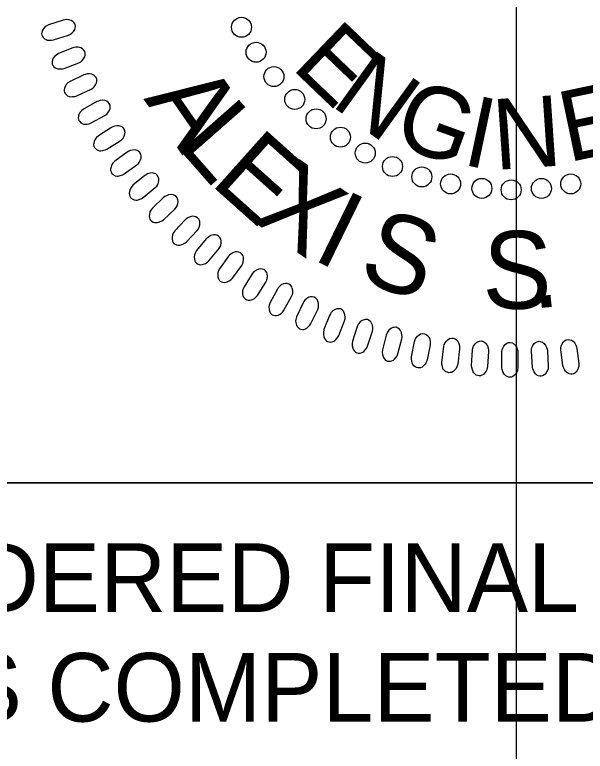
# Model space of a CAD drawing. Extents: x 497599 to 513368, y 404140 to 476034.
# Drawn here: x 507268.5 to 507314.2, y 439677.1 to 439736.2 of the extents above; entities that cross this region are included whole.
import ezdxf

# ---------------------------------------------------------------- set-up
doc = ezdxf.new("R2010")
doc.units = 0
for name, color, linetype in [('Sheet Layout Profile Border Port 2', 7, 'Continuous'), ('Sheet PE Seal Cell', 7, 'Continuous'), ('Sheet Profile CELL', 7, 'Continuous'), ('Sheet Sticker Exception Certification CELL', 7, 'Continuous')]:
    doc.layers.add(name, color=color, linetype=linetype)

msp = doc.modelspace()

# ---------------------------------------------------------------- linework, layer by layer
at = {"layer": 'Sheet Layout Profile Border Port 2'}
msp.add_lwpolyline([(505908.678, 439836.144), (507308.678, 439836.144), (507308.678, 439336.144), (505908.678, 439336.144)], close=True, dxfattribs=at)
at = {"layer": 'Sheet PE Seal Cell'}
for points in [[(507272.361, 439735.737), (507271.194, 439735.358), (507270.997, 439735.255), (507270.88, 439735.163), (507270.753, 439735.003), (507270.679, 439734.877), (507270.638, 439734.746), (507270.632, 439734.634), (507270.648, 439734.521), (507270.702, 439734.421), (507270.767, 439734.316), (507270.856, 439734.235), (507270.983, 439734.167), (507271.077, 439734.134), (507271.241, 439734.116), (507271.43, 439734.115), (507271.589, 439734.143), (507272.786, 439734.523), (507272.94, 439734.597), (507273.059, 439734.683), (507273.183, 439734.818), (507273.281, 439734.967), (507273.328, 439735.084), (507273.336, 439735.252), (507273.309, 439735.401), (507273.225, 439735.53), (507273.145, 439735.615), (507273.011, 439735.705), (507272.813, 439735.766), (507272.621, 439735.775), (507272.489, 439735.763)], [(507273.12, 439733.5), (507271.979, 439733.049), (507271.788, 439732.933), (507271.677, 439732.833), (507271.561, 439732.667), (507271.495, 439732.536), (507271.462, 439732.402), (507271.464, 439732.291), (507271.486, 439732.179), (507271.546, 439732.082), (507271.618, 439731.982), (507271.711, 439731.906), (507271.843, 439731.846), (507271.939, 439731.82), (507272.103, 439731.812), (507272.292, 439731.823), (507272.449, 439731.86), (507273.62, 439732.315), (507273.77, 439732.399), (507273.883, 439732.492), (507273.998, 439732.634), (507274.087, 439732.789), (507274.125, 439732.909), (507274.123, 439733.077), (507274.086, 439733.224), (507273.995, 439733.347), (507273.909, 439733.427), (507273.77, 439733.509), (507273.569, 439733.556), (507273.377, 439733.554), (507273.245, 439733.533)], [(507274.019, 439731.341), (507272.909, 439730.819), (507272.726, 439730.691), (507272.622, 439730.585), (507272.517, 439730.411), (507272.458, 439730.276), (507272.434, 439730.141), (507272.443, 439730.029), (507272.472, 439729.919), (507272.538, 439729.827), (507272.616, 439729.731), (507272.715, 439729.662), (507272.85, 439729.61), (507272.947, 439729.589), (507273.111, 439729.592), (507273.299, 439729.615), (507273.453, 439729.662), (507274.593, 439730.189), (507274.737, 439730.282), (507274.844, 439730.382), (507274.95, 439730.531), (507275.03, 439730.692), (507275.06, 439730.814), (507275.048, 439730.982), (507275.002, 439731.126), (507274.902, 439731.243), (507274.812, 439731.317), (507274.668, 439731.39), (507274.464, 439731.425), (507274.273, 439731.41), (507274.143, 439731.382)], [(507275.067, 439729.192), (507273.991, 439728.601), (507273.817, 439728.463), (507273.72, 439728.35), (507273.625, 439728.17), (507273.576, 439728.031), (507273.56, 439727.895), (507273.575, 439727.784), (507273.612, 439727.676), (507273.683, 439727.588), (507273.768, 439727.498), (507273.87, 439727.434), (507274.008, 439727.391), (507274.107, 439727.377), (507274.27, 439727.39), (507274.456, 439727.424), (507274.607, 439727.481), (507275.712, 439728.079), (507275.85, 439728.181), (507275.95, 439728.288), (507276.047, 439728.443), (507276.115, 439728.608), (507276.139, 439728.732), (507276.115, 439728.898), (507276.06, 439729.039), (507275.954, 439729.151), (507275.86, 439729.218), (507275.711, 439729.282), (507275.505, 439729.305), (507275.315, 439729.277), (507275.187, 439729.241)], [(507276.223, 439727.117), (507275.187, 439726.46), (507275.021, 439726.311), (507274.932, 439726.192), (507274.848, 439726.006), (507274.808, 439725.866), (507274.8, 439725.728), (507274.823, 439725.619), (507274.866, 439725.513), (507274.943, 439725.43), (507275.032, 439725.345), (507275.139, 439725.288), (507275.279, 439725.253), (507275.378, 439725.245), (507275.541, 439725.269), (507275.724, 439725.315), (507275.871, 439725.381), (507276.937, 439726.047), (507277.068, 439726.157), (507277.162, 439726.271), (507277.248, 439726.431), (507277.306, 439726.6), (507277.322, 439726.725), (507277.288, 439726.89), (507277.225, 439727.027), (507277.111, 439727.132), (507277.013, 439727.193), (507276.86, 439727.247), (507276.653, 439727.257), (507276.465, 439727.218), (507276.34, 439727.174)], [(507277.5, 439725.142), (507276.506, 439724.421), (507276.351, 439724.262), (507276.268, 439724.138), (507276.197, 439723.947), (507276.166, 439723.804), (507276.167, 439723.667), (507276.196, 439723.559), (507276.246, 439723.456), (507276.328, 439723.377), (507276.422, 439723.298), (507276.532, 439723.248), (507276.675, 439723.223), (507276.774, 439723.221), (507276.935, 439723.254), (507277.115, 439723.311), (507277.258, 439723.387), (507278.278, 439724.119), (507278.403, 439724.237), (507278.489, 439724.356), (507278.566, 439724.522), (507278.613, 439724.694), (507278.621, 439724.82), (507278.577, 439724.982), (507278.505, 439725.115), (507278.385, 439725.212), (507278.283, 439725.268), (507278.127, 439725.312), (507277.92, 439725.309), (507277.735, 439725.258), (507277.613, 439725.206)], [(507278.903, 439723.261), (507277.957, 439722.479), (507277.812, 439722.311), (507277.738, 439722.181), (507277.678, 439721.987), (507277.656, 439721.842), (507277.666, 439721.705), (507277.702, 439721.599), (507277.758, 439721.5), (507277.845, 439721.426), (507277.944, 439721.353), (507278.056, 439721.31), (507278.2, 439721.294), (507278.3, 439721.298), (507278.458, 439721.342), (507278.634, 439721.41), (507278.772, 439721.494), (507279.745, 439722.289), (507279.861, 439722.414), (507279.94, 439722.538), (507280.006, 439722.709), (507280.043, 439722.884), (507280.042, 439723.01), (507279.988, 439723.169), (507279.908, 439723.297), (507279.782, 439723.386), (507279.677, 439723.435), (507279.519, 439723.47), (507279.313, 439723.454), (507279.131, 439723.392), (507279.012, 439723.332)], [(507280.413, 439721.49), (507279.518, 439720.651), (507279.384, 439720.474), (507279.318, 439720.34), (507279.271, 439720.142), (507279.258, 439719.996), (507279.276, 439719.86), (507279.319, 439719.756), (507279.381, 439719.661), (507279.472, 439719.593), (507279.576, 439719.526), (507279.691, 439719.49), (507279.835, 439719.483), (507279.934, 439719.493), (507280.09, 439719.547), (507280.262, 439719.626), (507280.393, 439719.718), (507281.314, 439720.573), (507281.423, 439720.706), (507281.494, 439720.834), (507281.549, 439721.008), (507281.574, 439721.185), (507281.565, 439721.311), (507281.502, 439721.467), (507281.414, 439721.589), (507281.283, 439721.671), (507281.174, 439721.713), (507281.015, 439721.738), (507280.81, 439721.709), (507280.632, 439721.635), (507280.518, 439721.568)], [(507282.149, 439719.712), (507281.308, 439718.818), (507281.185, 439718.633), (507281.128, 439718.495), (507281.093, 439718.295), (507281.089, 439718.147), (507281.116, 439718.013), (507281.165, 439717.913), (507281.233, 439717.821), (507281.328, 439717.759), (507281.436, 439717.699), (507281.553, 439717.67), (507281.698, 439717.672), (507281.796, 439717.689), (507281.948, 439717.752), (507282.114, 439717.842), (507282.24, 439717.942), (507283.106, 439718.854), (507283.205, 439718.992), (507283.268, 439719.125), (507283.312, 439719.302), (507283.326, 439719.481), (507283.31, 439719.605), (507283.237, 439719.757), (507283.141, 439719.874), (507283.005, 439719.947), (507282.894, 439719.982), (507282.734, 439719.997), (507282.531, 439719.955), (507282.358, 439719.87), (507282.248, 439719.796)], [(507283.838, 439718.182), (507283.056, 439717.237), (507282.945, 439717.044), (507282.896, 439716.903), (507282.874, 439716.701), (507282.88, 439716.554), (507282.915, 439716.421), (507282.97, 439716.324), (507283.044, 439716.236), (507283.142, 439716.181), (507283.254, 439716.128), (507283.372, 439716.107), (507283.517, 439716.118), (507283.614, 439716.14), (507283.761, 439716.213), (507283.921, 439716.313), (507284.041, 439716.421), (507284.847, 439717.385), (507284.938, 439717.53), (507284.992, 439717.667), (507285.025, 439717.846), (507285.028, 439718.025), (507285.004, 439718.149), (507284.921, 439718.295), (507284.819, 439718.405), (507284.678, 439718.47), (507284.565, 439718.498), (507284.404, 439718.502), (507284.204, 439718.448), (507284.037, 439718.353), (507283.932, 439718.272)], [(507285.619, 439716.781), (507284.898, 439715.789), (507284.799, 439715.59), (507284.759, 439715.446), (507284.75, 439715.242), (507284.765, 439715.096), (507284.808, 439714.966), (507284.869, 439714.872), (507284.948, 439714.79), (507285.051, 439714.741), (507285.165, 439714.695), (507285.285, 439714.681), (507285.428, 439714.701), (507285.523, 439714.729), (507285.666, 439714.812), (507285.82, 439714.921), (507285.932, 439715.037), (507286.676, 439716.049), (507286.758, 439716.199), (507286.804, 439716.339), (507286.825, 439716.52), (507286.817, 439716.699), (507286.785, 439716.821), (507286.694, 439716.962), (507286.584, 439717.066), (507286.439, 439717.122), (507286.326, 439717.142), (507286.165, 439717.137), (507285.968, 439717.07), (507285.808, 439716.964), (507285.707, 439716.877)], [(507287.521, 439715.368), (507286.863, 439714.332), (507286.777, 439714.127), (507286.746, 439713.981), (507286.75, 439713.778), (507286.773, 439713.634), (507286.825, 439713.506), (507286.892, 439713.416), (507286.976, 439713.339), (507287.081, 439713.296), (507287.199, 439713.257), (507287.319, 439713.251), (507287.461, 439713.279), (507287.554, 439713.315), (507287.691, 439713.405), (507287.837, 439713.524), (507287.942, 439713.647), (507288.622, 439714.704), (507288.694, 439714.859), (507288.731, 439715.001), (507288.741, 439715.184), (507288.721, 439715.362), (507288.681, 439715.481), (507288.582, 439715.616), (507288.466, 439715.713), (507288.318, 439715.759), (507288.203, 439715.773), (507288.043, 439715.758), (507287.851, 439715.679), (507287.697, 439715.563), (507287.603, 439715.47)], [(507289.539, 439714.152), (507288.948, 439713.078), (507288.875, 439712.868), (507288.853, 439712.72), (507288.869, 439712.517), (507288.902, 439712.374), (507288.962, 439712.25), (507289.034, 439712.165), (507289.123, 439712.093), (507289.23, 439712.057), (507289.349, 439712.025), (507289.47, 439712.027), (507289.61, 439712.065), (507289.7, 439712.105), (507289.832, 439712.204), (507289.971, 439712.333), (507290.068, 439712.461), (507290.679, 439713.559), (507290.741, 439713.718), (507290.769, 439713.863), (507290.768, 439714.045), (507290.737, 439714.222), (507290.69, 439714.338), (507290.582, 439714.467), (507290.46, 439714.556), (507290.31, 439714.593), (507290.194, 439714.6), (507290.035, 439714.574), (507289.849, 439714.483), (507289.703, 439714.358), (507289.614, 439714.259)], [(507291.598, 439713.046), (507291.076, 439711.936), (507291.016, 439711.722), (507291.004, 439711.573), (507291.033, 439711.372), (507291.074, 439711.231), (507291.142, 439711.112), (507291.219, 439711.031), (507291.313, 439710.965), (507291.422, 439710.936), (507291.543, 439710.911), (507291.663, 439710.921), (507291.801, 439710.967), (507291.889, 439711.013), (507292.013, 439711.12), (507292.144, 439711.257), (507292.233, 439711.391), (507292.774, 439712.525), (507292.826, 439712.689), (507292.845, 439712.834), (507292.832, 439713.016), (507292.79, 439713.19), (507292.736, 439713.304), (507292.619, 439713.425), (507292.492, 439713.507), (507292.341, 439713.535), (507292.224, 439713.534), (507292.067, 439713.498), (507291.887, 439713.396), (507291.749, 439713.261), (507291.668, 439713.157)], [(507293.726, 439712.038), (507293.274, 439710.897), (507293.228, 439710.679), (507293.225, 439710.531), (507293.266, 439710.331), (507293.316, 439710.194), (507293.392, 439710.078), (507293.474, 439710.003), (507293.571, 439709.942), (507293.682, 439709.92), (507293.805, 439709.904), (507293.924, 439709.92), (507294.058, 439709.975), (507294.143, 439710.027), (507294.26, 439710.141), (507294.382, 439710.286), (507294.462, 439710.426), (507294.932, 439711.592), (507294.974, 439711.757), (507294.983, 439711.904), (507294.959, 439712.085), (507294.906, 439712.256), (507294.845, 439712.367), (507294.721, 439712.48), (507294.589, 439712.554), (507294.436, 439712.571), (507294.32, 439712.563), (507294.165, 439712.518), (507293.992, 439712.404), (507293.863, 439712.262), (507293.788, 439712.153)], [(507295.935, 439711.136), (507295.555, 439709.969), (507295.523, 439709.749), (507295.529, 439709.6), (507295.583, 439709.404), (507295.642, 439709.269), (507295.724, 439709.159), (507295.811, 439709.089), (507295.911, 439709.035), (507296.024, 439709.02), (507296.148, 439709.011), (507296.265, 439709.035), (507296.396, 439709.098), (507296.477, 439709.155), (507296.588, 439709.277), (507296.7, 439709.429), (507296.771, 439709.574), (507297.167, 439710.766), (507297.197, 439710.935), (507297.198, 439711.081), (507297.162, 439711.261), (507297.099, 439711.428), (507297.031, 439711.534), (507296.9, 439711.64), (507296.764, 439711.705), (507296.609, 439711.713), (507296.495, 439711.697), (507296.343, 439711.643), (507296.177, 439711.518), (507296.057, 439711.368), (507295.989, 439711.254)], [(507298.268, 439710.463), (507297.962, 439709.274), (507297.944, 439709.054), (507297.959, 439708.905), (507298.026, 439708.712), (507298.092, 439708.582), (507298.181, 439708.477), (507298.272, 439708.412), (507298.376, 439708.365), (507298.49, 439708.357), (507298.613, 439708.356), (507298.729, 439708.387), (507298.855, 439708.458), (507298.933, 439708.52), (507299.035, 439708.649), (507299.138, 439708.808), (507299.2, 439708.957), (507299.52, 439710.171), (507299.54, 439710.341), (507299.531, 439710.488), (507299.484, 439710.665), (507299.411, 439710.828), (507299.336, 439710.929), (507299.199, 439711.026), (507299.059, 439711.083), (507298.904, 439711.081), (507298.791, 439711.059), (507298.643, 439710.994), (507298.485, 439710.86), (507298.375, 439710.702), (507298.314, 439710.585)], [(507301.789, 439709.675), (507301.559, 439708.47), (507301.481, 439708.262), (507301.404, 439708.134), (507301.262, 439707.988), (507301.146, 439707.899), (507301.02, 439707.842), (507300.91, 439707.822), (507300.796, 439707.824), (507300.691, 439707.865), (507300.578, 439707.916), (507300.487, 439707.995), (507300.403, 439708.112), (507300.359, 439708.202), (507300.321, 439708.361), (507300.296, 439708.549), (507300.304, 439708.71), (507300.532, 439709.945), (507300.586, 439710.108), (507300.657, 439710.237), (507300.774, 439710.377), (507300.911, 439710.493), (507301.021, 439710.553), (507301.186, 439710.582), (507301.338, 439710.573), (507301.476, 439710.506), (507301.57, 439710.437), (507301.676, 439710.317), (507301.761, 439710.127), (507301.794, 439709.938), (507301.799, 439709.806)], [(507304.156, 439709.349), (507304.001, 439708.132), (507303.936, 439707.919), (507303.867, 439707.787), (507303.735, 439707.632), (507303.624, 439707.536), (507303.503, 439707.471), (507303.395, 439707.445), (507303.28, 439707.439), (507303.172, 439707.473), (507303.057, 439707.518), (507302.961, 439707.59), (507302.87, 439707.703), (507302.82, 439707.789), (507302.772, 439707.946), (507302.735, 439708.131), (507302.733, 439708.292), (507302.883, 439709.54), (507302.927, 439709.705), (507302.99, 439709.838), (507303.098, 439709.985), (507303.227, 439710.11), (507303.334, 439710.176), (507303.497, 439710.216), (507303.648, 439710.217), (507303.791, 439710.159), (507303.889, 439710.096), (507304.002, 439709.982), (507304.099, 439709.798), (507304.144, 439709.611), (507304.157, 439709.479)], [(507306.473, 439709.152), (507306.395, 439707.927), (507306.344, 439707.711), (507306.283, 439707.574), (507306.16, 439707.412), (507306.057, 439707.308), (507305.94, 439707.237), (507305.833, 439707.203), (507305.719, 439707.191), (507305.609, 439707.218), (507305.492, 439707.255), (507305.391, 439707.321), (507305.293, 439707.427), (507305.238, 439707.511), (507305.18, 439707.664), (507305.132, 439707.847), (507305.12, 439708.008), (507305.191, 439709.262), (507305.225, 439709.43), (507305.278, 439709.567), (507305.378, 439709.72), (507305.498, 439709.853), (507305.601, 439709.926), (507305.761, 439709.976), (507305.912, 439709.986), (507306.058, 439709.937), (507306.159, 439709.88), (507306.28, 439709.773), (507306.388, 439709.596), (507306.445, 439709.412), (507306.466, 439709.282)], [(507308.826, 439709.08), (507308.825, 439707.853), (507308.788, 439707.634), (507308.736, 439707.494), (507308.624, 439707.324), (507308.526, 439707.214), (507308.414, 439707.135), (507308.31, 439707.095), (507308.197, 439707.076), (507308.086, 439707.095), (507307.966, 439707.125), (507307.861, 439707.184), (507307.756, 439707.285), (507307.696, 439707.365), (507307.629, 439707.514), (507307.57, 439707.694), (507307.547, 439707.853), (507307.54, 439709.11), (507307.563, 439709.279), (507307.608, 439709.419), (507307.697, 439709.579), (507307.809, 439709.718), (507307.907, 439709.798), (507308.064, 439709.858), (507308.214, 439709.877), (507308.363, 439709.838), (507308.468, 439709.788), (507308.595, 439709.688), (507308.714, 439709.519), (507308.781, 439709.338), (507308.811, 439709.209)], [(507311.193, 439709.202), (507311.269, 439707.977), (507311.246, 439707.756), (507311.203, 439707.614), (507311.101, 439707.437), (507311.012, 439707.322), (507310.904, 439707.235), (507310.803, 439707.189), (507310.692, 439707.162), (507310.579, 439707.176), (507310.458, 439707.198), (507310.349, 439707.251), (507310.238, 439707.344), (507310.174, 439707.42), (507310.098, 439707.565), (507310.027, 439707.74), (507309.994, 439707.898), (507309.908, 439709.152), (507309.92, 439709.322), (507309.956, 439709.464), (507310.036, 439709.629), (507310.139, 439709.776), (507310.231, 439709.861), (507310.384, 439709.931), (507310.532, 439709.96), (507310.683, 439709.929), (507310.791, 439709.886), (507310.924, 439709.795), (507311.054, 439709.633), (507311.133, 439709.458), (507311.17, 439709.331)], [(507313.559, 439709.396), (507313.712, 439708.179), (507313.703, 439707.957), (507313.668, 439707.811), (507313.578, 439707.629), (507313.495, 439707.508), (507313.394, 439707.415), (507313.296, 439707.362), (507313.186, 439707.329), (507313.073, 439707.335), (507312.95, 439707.349), (507312.839, 439707.395), (507312.723, 439707.481), (507312.653, 439707.553), (507312.568, 439707.693), (507312.486, 439707.864), (507312.444, 439708.019), (507312.279, 439709.265), (507312.281, 439709.436), (507312.308, 439709.58), (507312.377, 439709.749), (507312.47, 439709.902), (507312.557, 439709.994), (507312.705, 439710.072), (507312.852, 439710.111), (507313.004, 439710.09), (507313.114, 439710.053), (507313.253, 439709.971), (507313.392, 439709.817), (507313.482, 439709.647), (507313.527, 439709.523)]]:
    msp.add_lwpolyline(points, close=True, dxfattribs=at)
for centre in [(507286.659, 439735.157), (507287.828, 439733.153), (507289.26, 439731.201), (507290.932, 439729.368), (507292.643, 439727.814), (507294.594, 439726.339), (507296.584, 439725.063), (507298.773, 439723.987), (507301.122, 439723.15), (507303.431, 439722.591), (507313.066, 439722.588), (507305.939, 439722.232), (507308.288, 439722.112), (507310.717, 439722.23)]:
    msp.add_circle(centre, 0.801, dxfattribs=at)
at = {"layer": 'Sheet Profile CELL'}
msp.add_lwpolyline([(507258.678, 439811.094), (507358.678, 439811.094), (507358.678, 439698.594), (507258.678, 439698.594)], close=True, dxfattribs=at)
at = {"layer": 'Sheet Sticker Exception Certification CELL'}
msp.add_line((507158.628, 439698.594), (507358.665, 439698.594), dxfattribs=at)
msp.add_line((507158.628, 439698.594), (507358.665, 439698.594), dxfattribs=at)

# ---------------------------------------------------------------- texts
at = {"layer": 'Sheet PE Seal Cell'}
for s, height, rotation, p in [('E', 5.669, 316.26559, (507290.581, 439731.919)), ('N', 5.669, 324.20538, (507293.716, 439728.964)), ('A', 6.236, 304.68345, (507278.779, 439729.417)), ('G', 5.669, 340.08498, (507298.61, 439725.865)), ('E', 5.669, 11.84417, (507312.84, 439724.31)), ('L', 6.236, 311.30312, (507281.319, 439725.737)), ('I', 5.669, 348.02477, (507304.239, 439724.176)), ('N', 5.669, 3.90437, (507306.992, 439723.703)), ('E', 6.236, 318.14878, (507284.033, 439722.656)), ('X', 6.236, 324.99444, (507287.434, 439719.683)), ('I', 6.236, 333.94176, (507292.183, 439716.622)), ('S', 6.236, 340.78741, (507295.839, 439714.929)), ('S', 6.236, 359.38261, (507305.96, 439712.606)), ('.', 6.236, 6.22827, (507309.999, 439712.557))]:
    msp.add_text(s, height=height, rotation=rotation, dxfattribs=at).set_placement(p)
at = {"layer": 'Sheet Sticker Exception Certification CELL'}
for s, p in [('DOCUMENT NOT CONSIDERED FINAL', (507179.698, 439688.249)), ('DOCUMENT NOT CONSIDERED FINAL', (507179.698, 439688.249)), ('UNLESS ALL SIGNATURES COMPLETED', (507174.627, 439679.449)), ('UNLESS ALL SIGNATURES COMPLETED', (507174.627, 439679.449))]:
    msp.add_text(s, height=5.5, dxfattribs=at).set_placement(p)

doc.saveas('drawing.dxf')
